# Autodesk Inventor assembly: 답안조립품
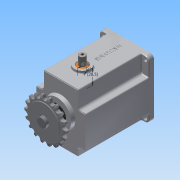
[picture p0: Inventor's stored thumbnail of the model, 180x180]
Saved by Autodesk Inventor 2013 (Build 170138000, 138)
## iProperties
Created: 2016-05
Part Number: 답안조립품
Document SubType Name: Assembly
Designer: Administrator
Mass: 2686.24 g
Surface Area: 1920.96 cm^2
Volume: 707.57 cm^3
Density: 3.79642 g/cm^3
Author: Administrator
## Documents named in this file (16)
- C:\Users\Administrator\Desktop\360508V1009\답안조립품.iam
- C:\Users\Administrator\Desktop\360508V1009\본체.ipt
- C:\Users\Administrator\Desktop\360508V1009\오일실 8 22 7.ipt
- C:\Users\Administrator\Desktop\360508V1009\오일실 17 32 8.ipt
- C:\Users\Administrator\Desktop\360508V1009\커버.ipt
- C:\Users\Administrator\Desktop\360508V1009\베어링 608.ipt
- C:\Users\Administrator\Desktop\360508V1009\메인축.ipt
- C:\Users\Administrator\Desktop\360508V1009\서브축.ipt
- C:\Users\Administrator\Desktop\360508V1009\베어링 6003.ipt
- C:\Users\Administrator\Desktop\360508V1009\스프로킷.ipt
- C:\Users\Administrator\Desktop\360508V1009\키 5 x 5 x 18.ipt
- C:\Users\Administrator\Desktop\360508V1009\멈춤나사 M3x8.ipt
- C:\Users\Administrator\Desktop\360508V1009\부시.ipt
- C:\Users\Administrator\Desktop\360508V1009\슬라이더.ipt
- C:\Users\Administrator\Desktop\360508V1009\가변스프링.ipt
- C:\Users\Administrator\Desktop\360508V1009\볼트 M4 x 10.ipt
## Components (3 placed, 2 different names)
1. 가변스프링:1
2. ISO 4762 M4 x 10:1
3. ISO 4762 M4 x 10:2
